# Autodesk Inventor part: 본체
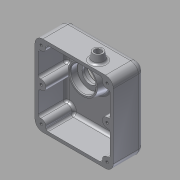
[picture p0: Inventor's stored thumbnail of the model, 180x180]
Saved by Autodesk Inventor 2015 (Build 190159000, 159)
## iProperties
Created: 2015-10
Part Number: 본체
Material: 알루미늄 6061
Document SubType Name: Modeling
Designer: mduedu
Density: 2.71 g/cm^3
Appearance: 알루미늄 - 평지
Mass: 323.56 g
Surface Area: 515.791 cm^2
Volume: 119.395 cm^3
Author: mduedu
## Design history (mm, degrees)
sketch "스케치1"
  geometry: L1 (-50, -51.5)-(50, -51.5); L2 (50, -51.5)-(50, 51.5); L3 (50, 51.5)-(-50, 51.5); L4 (-50, 51.5)-(-50, -51.5); L5 (-50, -51.5)-(50, 51.5); L6 (50, -51.5)-(-50, 51.5); 1 further point
  constraints: 12 end point, 2 midpoint, 2 parallel, 1 horizontal, 1 perpendicular
  dimensions: "d0" = 100 distance of L3.end L2.end; "d1" = 103 distance of L2.end L1.end
extrude "돌출1" new body sketch "스케치1" distance "d2" = 40; taper "d3" = 0 deg
fillet "모깎기1" dims "d4" = 10
fillet "모깎기2" dims "d5" = 8
feature "쉘1" dims "d6" = 4
sketch "스케치2"
  geometry: L1 (-50, 41.5)-(-50, -41.5) reference; L2 (50, -41.5)-(50, 41.5) reference; L3 (-50, 0)-(50, 0); L4 (40, 51.5)-(-40, 51.5) reference; L5 (-40, -51.5)-(40, -51.5) reference; L6 (0, 51.5)-(0, -51.5); C1 r 6 at (-42, 43.5); C2 r 6 at (-42, 0); C3 r 6 at (-42, -43.5); C4 r 6 at (42, 43.5); C5 r 6 at (42, 0); C6 r 6 at (42, -43.5); 1 further point
  constraints: 6 centre point, 4 end point, 4 midpoint, 4 symmetric about line, 1 point on line, 1 vertical alignment, 4 other
  dimensions: "d7" = 12 diameter of C1; "d10" = 12 diameter of C2 (= d7); "d16" = 8 distance from line of C1.centre L1; "d17" = 8 distance from line of C1.centre L4
extrude "돌출2" join sketch "스케치2" stored distance "d11" = 0; taper "d12" = 0 deg
fillet "모깎기3" dims "d13" = 3
sketch "스케치3"
  geometry: A1 r 6 centre (-42, 43.5) between (-42.667, 37.537) and (-36.037, 44.167) reference; A2 r 6 centre (42, 43.5) between (36.037, 44.167) and (42.667, 37.537) reference; A3 r 6 centre (42, 0) between (42.667, 5.963) and (42.667, -5.963) reference; A4 r 6 centre (-42, 0) between (-42.667, -5.963) and (-42.667, 5.963) reference; A5 r 6 centre (-42, -43.5) between (-36.037, -44.167) and (-42.667, -37.537) reference; A6 r 6 centre (42, -43.5) between (42.667, -37.537) and (36.037, -44.167) reference; 7 further points
  constraints: 6 coincident
hole "구멍1" sketch "스케치3" at (-42, 43.5), (-42, 0), (-42, -43.5), (42, -43.5), (42, 0), (42, 43.5) diameter "d18" = 3.242; stored, may be unused: countersink angle "d22" = 90 deg, drill point angle "d24" = 118 deg; dims "d19" = 12, "d20" = 4, "d21" = 2, "d23" = 14
sketch "스케치4"
  geometry: L1 (90, 0)-(80, 0) reference; L2 (90, 0)-(90, 32) reference; C1 r 8 at (58.594, 12); 1 further point
  constraints: 1 centre point
  dimensions: "d25" = 16 diameter of C1; "d26" = 12 distance from line of L1 C1.centre; "d27" = 31.406 distance from line of C1.centre L2
extrude "돌출3" join sketch "스케치4" distance "d28" = 10; taper "d29" = -10 deg
sketch "스케치5"
  geometry: C1 r 8 at (0, 0) reference; C2 r 4 at (0, 0); 1 further point
  constraints: 1 centre point, 1 coincident
  dimensions: "d30" = 8 diameter of C2
extrude "돌출4" cut sketch "스케치5" stored distance "d31" = 0; taper "d32" = 0 deg
chamfer "모따기1" distance "d33" = 0.5; stored, may be unused: second distance "d34" = 2, angle "d35" = 45 deg
fillet "모깎기4" dims "d36" = 3
sketch "스케치6"
  geometry: L1 (73, 8)-(-7, 8) reference; L2 (-17, -2)-(-17, -85) reference; C1 r 21.5 at (23, -32); 1 further point
  constraints: 1 centre point
  dimensions: "d37" = 43 diameter of C1; "d38" = 40 distance from line of C1.centre L1; "d39" = 40 distance from line of C1.centre L2
extrude "돌출5" join sketch "스케치6" distance "d40" = 15; taper "d41" = -10 deg
hole "구멍2" diameter "d44" = 25; stored, may be unused: countersink angle "d48" = 90 deg, drill point angle "d50" = 0 deg; dims "d42" = 10, "d43" = 10, "d45" = 10, "d46" = 4, "d47" = 2, "d49" = 7
hole "구멍3" diameter "d53" = 20; stored, may be unused: countersink angle "d57" = 90 deg, drill point angle "d59" = 0 deg; dims "d51" = 10, "d52" = 10, "d54" = 10, "d55" = 32, "d56" = 9, "d58" = 7
chamfer "모따기2" distance "d60" = 1; stored, may be unused: second distance "d61" = 2, angle "d62" = 45 deg
sketch "스케치7"
  geometry: L1 (-50, 41.5)-(-50, -41.5) reference; L2 (-40, -51.5)-(40, -51.5) reference; 2 further points
  constraints: 1 other
  dimensions: "d63" = 50 distance from line of point (0, -21.5) L1; "d64" = 30 distance from line of point (0, -21.5) L2
feature "엠보싱1" sketch "스케치7" dims "d0" = 100, "d1" = 103, "d65" = 0.5, "d66" = 0
fillet "모깎기5" dims "d67" = 3
fillet "모깎기6" dims "d68" = 0.3
chamfer "모따기3" distance "d69" = 0.5; stored, may be unused: second distance "d70" = 2, angle "d71" = 45 deg
node "솔리드1"
